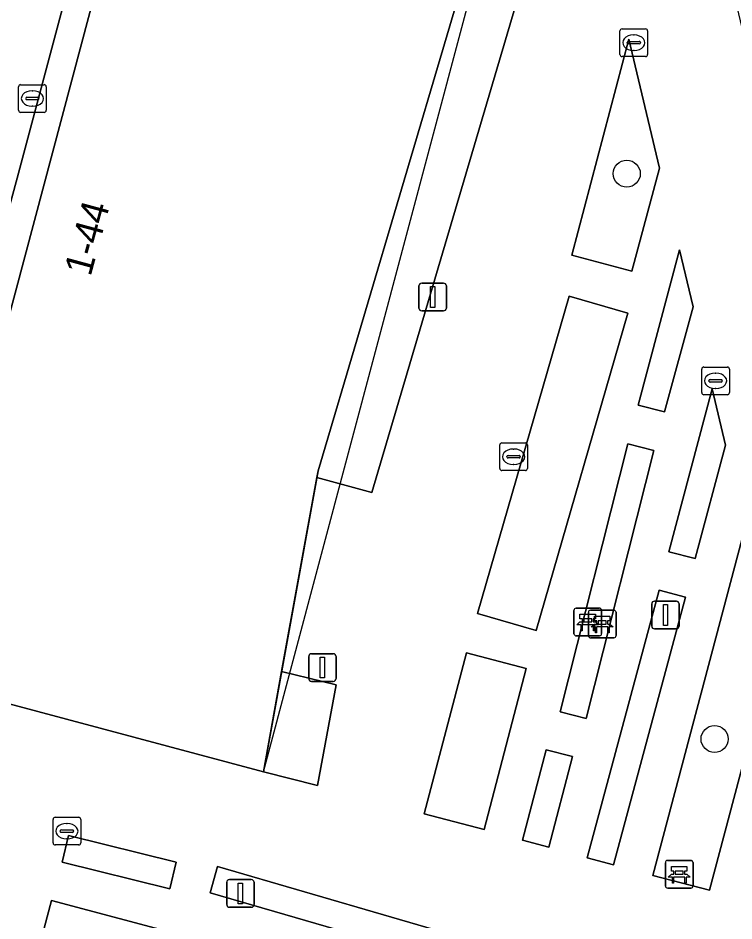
# Model space of a CAD drawing. Extents: x 160675 to 161153, y 383241 to 383714.
# Drawn here: x 160862.26 to 160888.14, y 383503.84 to 383536.47 of the extents above; entities that cross this region are included whole.
import ezdxf

# ---------------------------------------------------------------- set-up
doc = ezdxf.new("R2010")
doc.units = 0
for name, color, linetype in [('IMGEO_Bank', 7, 'Continuous'), ('IMGEO_Boom', 7, 'Continuous'), ('IMGEO_Groenvoorziening', 7, 'Continuous'), ('IMGEO_Kolk', 7, 'Continuous'), ('IMGEO_Lichtmast', 7, 'Continuous'), ('IMGEO_Pand', 7, 'Continuous'), ('IMGEO_Pand_nummerreeks', 7, 'Continuous'), ('IMGEO_Pand_overbouw', 7, 'Continuous'), ('IMGEO_Terreindeel_open', 7, 'Continuous'), ('IMGEO_Voetpad_open', 7, 'Continuous')]:
    doc.layers.add(name, color=color, linetype=linetype)

msp = doc.modelspace()

# ---------------------------------------------------------------- linework, layer by layer
at = {"layer": 'IMGEO_Bank'}
for p, q in [((160882.357, 383514.22), (160882.357, 383515.061)), ((160882.357, 383515.061), (160882.357, 383514.22)), ((160882.432, 383515.145), (160883.273, 383515.145)), ((160883.273, 383515.145), (160882.432, 383515.145)), ((160882.953, 383515.071), (160883.794, 383515.071)), ((160883.794, 383515.071), (160882.953, 383515.071)), ((160883.357, 383515.07), (160883.357, 383514.229)), ((160883.357, 383514.229), (160883.357, 383515.07)), ((160882.666, 383514.651), (160882.666, 383514.757)), ((160882.71, 383514.757), (160882.71, 383514.651)), ((160882.998, 383514.763), (160882.716, 383514.763)), ((160882.878, 383514.146), (160882.878, 383514.987)), ((160882.878, 383514.987), (160882.878, 383514.146)), ((160883.004, 383514.651), (160883.004, 383514.757)), ((160883.048, 383514.757), (160883.048, 383514.651)), ((160883.519, 383514.689), (160883.237, 383514.689)), ((160883.878, 383514.996), (160883.878, 383514.155)), ((160883.878, 383514.155), (160883.878, 383514.996)), ((160883.054, 383514.543), (160882.661, 383514.543)), ((160882.716, 383514.645), (160882.998, 383514.645)), ((160883.575, 383514.469), (160883.182, 383514.469)), ((160883.187, 383514.577), (160883.187, 383514.683)), ((160883.231, 383514.683), (160883.231, 383514.577)), ((160883.237, 383514.571), (160883.519, 383514.571)), ((160883.525, 383514.577), (160883.525, 383514.683)), ((160883.569, 383514.683), (160883.569, 383514.577)), ((160883.282, 383514.145), (160882.441, 383514.145)), ((160882.441, 383514.145), (160883.282, 383514.145)), ((160883.803, 383514.071), (160882.962, 383514.071)), ((160882.962, 383514.071), (160883.803, 383514.071)), ((160885.661, 383505.101), (160885.661, 383505.942)), ((160885.661, 383505.942), (160885.661, 383505.101)), ((160885.736, 383506.026), (160886.577, 383506.026)), ((160886.577, 383506.026), (160885.736, 383506.026)), ((160886.661, 383505.951), (160886.661, 383505.11)), ((160886.661, 383505.11), (160886.661, 383505.951)), ((160885.97, 383505.532), (160885.97, 383505.638)), ((160886.014, 383505.638), (160886.014, 383505.532)), ((160886.302, 383505.644), (160886.02, 383505.644)), ((160886.308, 383505.532), (160886.308, 383505.638)), ((160886.352, 383505.638), (160886.352, 383505.532)), ((160886.358, 383505.424), (160885.965, 383505.424)), ((160886.02, 383505.526), (160886.302, 383505.526)), ((160886.586, 383505.026), (160885.745, 383505.026)), ((160885.745, 383505.026), (160886.586, 383505.026))]:
    msp.add_line(p, q, dxfattribs=at)
for points in [[(160882.66, 383514.763), (160882.574, 383514.763), (160882.574, 383514.924), (160883.137, 383514.924), (160883.137, 383514.763), (160883.054, 383514.763)], [(160883.181, 383514.689), (160883.095, 383514.689), (160883.095, 383514.85), (160883.658, 383514.85), (160883.658, 383514.689), (160883.575, 383514.689)], [(160882.604, 383514.543), (160882.462, 383514.543), (160882.574, 383514.645), (160882.66, 383514.645)], [(160882.654, 383514.536), (160882.654, 383514.329), (160882.611, 383514.329), (160882.611, 383514.536)], [(160883.125, 383514.469), (160882.983, 383514.469), (160883.095, 383514.571), (160883.181, 383514.571)], [(160883.054, 383514.645), (160883.137, 383514.645), (160883.249, 383514.543), (160883.11, 383514.543)], [(160883.104, 383514.536), (160883.104, 383514.329), (160883.06, 383514.329), (160883.06, 383514.536)], [(160883.175, 383514.462), (160883.175, 383514.255), (160883.132, 383514.255), (160883.132, 383514.462)], [(160883.575, 383514.571), (160883.658, 383514.571), (160883.77, 383514.469), (160883.631, 383514.469)], [(160883.625, 383514.462), (160883.625, 383514.255), (160883.581, 383514.255), (160883.581, 383514.462)], [(160885.964, 383505.644), (160885.878, 383505.644), (160885.878, 383505.805), (160886.441, 383505.805), (160886.441, 383505.644), (160886.358, 383505.644)], [(160885.908, 383505.424), (160885.766, 383505.424), (160885.878, 383505.526), (160885.964, 383505.526)], [(160885.958, 383505.417), (160885.958, 383505.21), (160885.915, 383505.21), (160885.915, 383505.417)], [(160886.358, 383505.526), (160886.441, 383505.526), (160886.553, 383505.424), (160886.414, 383505.424)], [(160886.408, 383505.417), (160886.408, 383505.21), (160886.364, 383505.21), (160886.364, 383505.417)]]:
    msp.add_lwpolyline(points, dxfattribs=at)
for centre, radius, start, end in [((160882.435, 383515.067), 0.0779, 92.4484, 184.2845), ((160882.435, 383515.067), 0.0779, 92.4484, 184.2845), ((160882.956, 383514.993), 0.0779, 92.4484, 184.2845), ((160882.956, 383514.993), 0.0779, 92.4484, 184.2845), ((160883.279, 383515.067), 0.0779, 2.4484, 94.2845), ((160883.279, 383515.067), 0.0779, 2.4484, 94.2845), ((160883.8, 383514.993), 0.0779, 2.4484, 94.2845), ((160883.8, 383514.993), 0.0779, 2.4484, 94.2845), ((160882.659, 383514.756), 0.00671, 2.8957, 87.1043), ((160882.716, 383514.756), 0.00671, 92.8957, 177.1043), ((160882.998, 383514.756), 0.00671, 2.8957, 87.1043), ((160883.055, 383514.756), 0.00671, 92.8957, 177.1043), ((160883.18, 383514.682), 0.00671, 2.8957, 87.1043), ((160883.237, 383514.682), 0.00671, 92.8957, 177.1043), ((160883.519, 383514.682), 0.00671, 2.8957, 87.1043), ((160883.576, 383514.682), 0.00671, 92.8957, 177.1043), ((160882.604, 383514.536), 0.00671, 2.8957, 87.1043), ((160882.661, 383514.536), 0.00671, 92.8957, 177.1043), ((160882.659, 383514.652), 0.00671, 272.8957, 357.1043), ((160882.716, 383514.652), 0.00671, 182.8957, 267.1043), ((160882.998, 383514.652), 0.00671, 272.8957, 357.1043), ((160883.055, 383514.652), 0.00671, 182.8957, 267.1043), ((160883.053, 383514.536), 0.00671, 2.8957, 87.1043), ((160883.11, 383514.536), 0.00671, 92.8957, 177.1043), ((160883.125, 383514.462), 0.00671, 2.8957, 87.1043), ((160883.182, 383514.462), 0.00671, 92.8957, 177.1043), ((160883.18, 383514.578), 0.00671, 272.8957, 357.1043), ((160883.237, 383514.578), 0.00671, 182.8957, 267.1043), ((160883.519, 383514.578), 0.00671, 272.8957, 357.1043), ((160883.576, 383514.578), 0.00671, 182.8957, 267.1043), ((160883.574, 383514.462), 0.00671, 2.8957, 87.1043), ((160883.631, 383514.462), 0.00671, 92.8957, 177.1043), ((160882.435, 383514.223), 0.0779, 182.4484, 274.2845), ((160882.435, 383514.223), 0.0779, 182.4484, 274.2845), ((160882.956, 383514.149), 0.0779, 182.4484, 274.2845), ((160882.956, 383514.149), 0.0779, 182.4484, 274.2845), ((160883.279, 383514.223), 0.0779, 272.4484, 4.2845), ((160883.279, 383514.223), 0.0779, 272.4484, 4.2845), ((160883.8, 383514.149), 0.0779, 272.4484, 4.2845), ((160883.8, 383514.149), 0.0779, 272.4484, 4.2845), ((160885.739, 383505.948), 0.0779, 92.4484, 184.2845), ((160885.739, 383505.948), 0.0779, 92.4484, 184.2845), ((160886.583, 383505.948), 0.0779, 2.4484, 94.2845), ((160886.583, 383505.948), 0.0779, 2.4484, 94.2845), ((160885.963, 383505.637), 0.00671, 2.8957, 87.1043), ((160886.02, 383505.637), 0.00671, 92.8957, 177.1043), ((160886.302, 383505.637), 0.00671, 2.8957, 87.1043), ((160886.359, 383505.637), 0.00671, 92.8957, 177.1043), ((160885.908, 383505.417), 0.00671, 2.8957, 87.1043), ((160885.965, 383505.417), 0.00671, 92.8957, 177.1043), ((160885.963, 383505.533), 0.00671, 272.8957, 357.1043), ((160886.02, 383505.533), 0.00671, 182.8957, 267.1043), ((160886.302, 383505.533), 0.00671, 272.8957, 357.1043), ((160886.359, 383505.533), 0.00671, 182.8957, 267.1043), ((160886.357, 383505.417), 0.00671, 2.8957, 87.1043), ((160886.414, 383505.417), 0.00671, 92.8957, 177.1043), ((160885.739, 383505.104), 0.0779, 182.4484, 274.2845), ((160885.739, 383505.104), 0.0779, 182.4484, 274.2845), ((160886.583, 383505.104), 0.0779, 272.4484, 4.2845), ((160886.583, 383505.104), 0.0779, 272.4484, 4.2845)]:
    msp.add_arc(centre, radius, start, end, dxfattribs=at)
at = {"layer": 'IMGEO_Boom'}
for centre in [(160884.265, 383530.85), (160887.439, 383510.414)]:
    msp.add_circle(centre, 0.489, dxfattribs=at)
at = {"layer": 'IMGEO_Groenvoorziening'}
for points in [[(160882.404, 383551.516), (160882.765, 383552.718), (160867.046, 383548.766), (160862.229, 383530.692), (160857.402, 383512.924), (160858.445, 383512.624), (160866.56, 383543.07), (160867.863, 383547.958), (160869.136, 383548.269)], [(160885.452, 383531.052), (160884.337, 383535.716), (160882.275, 383527.908), (160884.45, 383527.328)], [(160886.165, 383528.095), (160884.676, 383522.483), (160885.625, 383522.243), (160886.664, 383526.034)], [(160880.989, 383514.338), (160884.301, 383525.812), (160882.182, 383526.424), (160878.87, 383514.95)], [(160886.734, 383516.939), (160887.837, 383521.04), (160887.355, 383523.068), (160885.788, 383517.177)], [(160884.3, 383521.082), (160881.855, 383511.395), (160882.802, 383511.156), (160885.247, 383520.843)], [(160888.545, 383518.071), (160885.21, 383505.485), (160887.26, 383504.948), (160889.58, 383513.712)], [(160882.838, 383506.122), (160883.787, 383505.867), (160886.389, 383515.541), (160885.44, 383515.796)], [(160876.945, 383507.705), (160879.106, 383507.14), (160880.632, 383512.969), (160878.471, 383513.535)], [(160871.79, 383512.852), (160871.132, 383509.231), (160873.089, 383508.73), (160873.758, 383512.376)], [(160882.309, 383509.777), (160881.356, 383510.028), (160880.496, 383506.755), (160881.449, 383506.505)], [(160863.855, 383505.962), (160867.746, 383505), (160867.984, 383505.963), (160864.093, 383506.925)], [(160882.056, 383502.15), (160869.476, 383505.805), (160869.202, 383504.86), (160881.782, 383501.206)], [(160863.476, 383504.573), (160862.947, 383502.579), (160875.539, 383499.24), (160876.068, 383501.233)]]:
    msp.add_lwpolyline(points, close=True, dxfattribs=at)
at = {"layer": 'IMGEO_Kolk'}
for p, q in [((160884.018, 383535.157), (160884.018, 383536.009)), ((160884.093, 383536.083), (160884.945, 383536.083)), ((160885.019, 383536.009), (160885.019, 383535.157)), ((160884.277, 383535.577), (160884.277, 383535.589)), ((160884.32, 383535.626), (160884.718, 383535.626)), ((160884.506, 383535.863), (160884.531, 383535.863)), ((160884.761, 383535.589), (160884.761, 383535.577)), ((160884.715, 383535.54), (160884.317, 383535.54)), ((160884.529, 383535.303), (160884.504, 383535.303)), ((160884.945, 383535.083), (160884.093, 383535.083)), ((160862.282, 383533.14), (160862.282, 383533.992)), ((160862.357, 383534.066), (160863.209, 383534.066)), ((160863.283, 383533.992), (160863.283, 383533.14)), ((160862.77, 383533.846), (160862.795, 383533.846)), ((160862.541, 383533.56), (160862.541, 383533.572)), ((160862.979, 383533.523), (160862.581, 383533.523)), ((160862.584, 383533.609), (160862.982, 383533.609)), ((160863.025, 383533.572), (160863.025, 383533.56)), ((160863.209, 383533.066), (160862.357, 383533.066)), ((160862.793, 383533.286), (160862.768, 383533.286)), ((160887.05, 383523.861), (160887.902, 383523.861)), ((160886.975, 383522.935), (160886.975, 383523.787)), ((160887.463, 383523.641), (160887.488, 383523.641)), ((160887.976, 383523.787), (160887.976, 383522.935)), ((160887.234, 383523.355), (160887.234, 383523.367)), ((160887.672, 383523.318), (160887.274, 383523.318)), ((160887.277, 383523.404), (160887.675, 383523.404)), ((160887.718, 383523.367), (160887.718, 383523.355)), ((160887.902, 383522.861), (160887.05, 383522.861)), ((160887.486, 383523.081), (160887.461, 383523.081)), ((160879.675, 383520.191), (160879.675, 383521.043)), ((160879.75, 383521.117), (160880.602, 383521.117)), ((160880.163, 383520.897), (160880.188, 383520.897)), ((160880.676, 383521.043), (160880.676, 383520.191)), ((160879.934, 383520.611), (160879.934, 383520.623)), ((160880.372, 383520.574), (160879.974, 383520.574)), ((160879.977, 383520.66), (160880.375, 383520.66)), ((160880.418, 383520.623), (160880.418, 383520.611)), ((160880.186, 383520.337), (160880.161, 383520.337)), ((160880.602, 383520.117), (160879.75, 383520.117)), ((160863.529, 383506.658), (160863.529, 383507.51)), ((160863.604, 383507.584), (160864.456, 383507.584)), ((160864.53, 383507.51), (160864.53, 383506.658)), ((160864.017, 383507.364), (160864.042, 383507.364)), ((160863.788, 383507.078), (160863.788, 383507.09)), ((160864.226, 383507.041), (160863.828, 383507.041)), ((160863.831, 383507.127), (160864.229, 383507.127)), ((160864.272, 383507.09), (160864.272, 383507.078)), ((160864.456, 383506.584), (160863.604, 383506.584)), ((160864.04, 383506.804), (160864.015, 383506.804))]:
    msp.add_line(p, q, dxfattribs=at)
for points in [[(160884.018, 383535.157), (160884.018, 383536.009)], [(160884.093, 383536.083), (160884.945, 383536.083)], [(160885.019, 383536.009), (160885.019, 383535.157)], [(160884.945, 383535.083), (160884.093, 383535.083)], [(160862.282, 383533.14), (160862.282, 383533.992)], [(160862.357, 383534.066), (160863.209, 383534.066)], [(160863.283, 383533.992), (160863.283, 383533.14)], [(160863.209, 383533.066), (160862.357, 383533.066)], [(160887.05, 383523.861), (160887.902, 383523.861)], [(160886.975, 383522.935), (160886.975, 383523.787)], [(160887.976, 383523.787), (160887.976, 383522.935)], [(160887.902, 383522.861), (160887.05, 383522.861)], [(160879.675, 383520.191), (160879.675, 383521.043)], [(160879.75, 383521.117), (160880.602, 383521.117)], [(160880.676, 383521.043), (160880.676, 383520.191)], [(160880.602, 383520.117), (160879.75, 383520.117)], [(160863.529, 383506.658), (160863.529, 383507.51)], [(160863.604, 383507.584), (160864.456, 383507.584)], [(160864.53, 383507.51), (160864.53, 383506.658)], [(160864.456, 383506.584), (160863.604, 383506.584)]]:
    msp.add_lwpolyline(points, dxfattribs=at)
for centre, radius, start, end in [((160884.095, 383536.007), 0.0765, 91.552, 178.448), ((160884.095, 383536.007), 0.0765, 91.552, 178.448), ((160884.943, 383536.007), 0.0765, 1.552, 88.448), ((160884.943, 383536.007), 0.0765, 1.552, 88.448), ((160884.317, 383535.586), 0.0403, 85.8775, 175.7526), ((160884.314, 383535.576), 0.0366, 178.938, 274.7102), ((160884.718, 383535.583), 0.043, 264.8664, 352.4533), ((160884.722, 383535.588), 0.0386, 1.7309, 96.639), ((160884.095, 383535.159), 0.0765, 181.552, 268.448), ((160884.095, 383535.159), 0.0765, 181.552, 268.448), ((160884.943, 383535.159), 0.0765, 271.552, 358.448), ((160884.943, 383535.159), 0.0765, 271.552, 358.448), ((160862.359, 383533.99), 0.0765, 91.552, 178.448), ((160862.359, 383533.99), 0.0765, 91.552, 178.448), ((160863.207, 383533.99), 0.0765, 1.552, 88.448), ((160863.207, 383533.99), 0.0765, 1.552, 88.448), ((160862.581, 383533.569), 0.0403, 85.8775, 175.7526), ((160862.578, 383533.559), 0.0366, 178.938, 274.7102), ((160862.982, 383533.566), 0.043, 264.8664, 352.4533), ((160862.986, 383533.571), 0.0386, 1.7309, 96.639), ((160862.359, 383533.142), 0.0765, 181.552, 268.448), ((160862.359, 383533.142), 0.0765, 181.552, 268.448), ((160863.207, 383533.142), 0.0765, 271.552, 358.448), ((160863.207, 383533.142), 0.0765, 271.552, 358.448), ((160887.052, 383523.785), 0.0765, 91.552, 178.448), ((160887.052, 383523.785), 0.0765, 91.552, 178.448), ((160887.9, 383523.785), 0.0765, 1.552, 88.448), ((160887.9, 383523.785), 0.0765, 1.552, 88.448), ((160887.274, 383523.364), 0.0403, 85.8775, 175.7526), ((160887.271, 383523.354), 0.0366, 178.938, 274.7102), ((160887.675, 383523.361), 0.043, 264.8664, 352.4533), ((160887.679, 383523.366), 0.0386, 1.7309, 96.639), ((160887.052, 383522.937), 0.0765, 181.552, 268.448), ((160887.052, 383522.937), 0.0765, 181.552, 268.448), ((160887.9, 383522.937), 0.0765, 271.552, 358.448), ((160887.9, 383522.937), 0.0765, 271.552, 358.448), ((160879.752, 383521.041), 0.0765, 91.552, 178.448), ((160879.752, 383521.041), 0.0765, 91.552, 178.448), ((160880.6, 383521.041), 0.0765, 1.552, 88.448), ((160880.6, 383521.041), 0.0765, 1.552, 88.448), ((160879.974, 383520.62), 0.0403, 85.8775, 175.7526), ((160879.971, 383520.61), 0.0366, 178.938, 274.7102), ((160880.375, 383520.617), 0.043, 264.8664, 352.4533), ((160880.379, 383520.622), 0.0386, 1.7309, 96.639), ((160879.752, 383520.193), 0.0765, 181.552, 268.448), ((160879.752, 383520.193), 0.0765, 181.552, 268.448), ((160880.6, 383520.193), 0.0765, 271.552, 358.448), ((160880.6, 383520.193), 0.0765, 271.552, 358.448), ((160863.606, 383507.508), 0.0765, 91.552, 178.448), ((160863.606, 383507.508), 0.0765, 91.552, 178.448), ((160864.454, 383507.508), 0.0765, 1.552, 88.448), ((160864.454, 383507.508), 0.0765, 1.552, 88.448), ((160863.828, 383507.087), 0.0403, 85.8775, 175.7526), ((160863.825, 383507.077), 0.0366, 178.938, 274.7102), ((160864.229, 383507.084), 0.043, 264.8664, 352.4533), ((160864.233, 383507.089), 0.0386, 1.7309, 96.639), ((160863.606, 383506.66), 0.0765, 181.552, 268.448), ((160863.606, 383506.66), 0.0765, 181.552, 268.448), ((160864.454, 383506.66), 0.0765, 271.552, 358.448), ((160864.454, 383506.66), 0.0765, 271.552, 358.448)]:
    msp.add_arc(centre, radius, start, end, dxfattribs=at)
for centre, major_axis, ratio, start_param, end_param in [((160884.505, 383535.583), (-0.387, 0.002), 0.722429, 4.712389, 7.853982), ((160884.53, 383535.583), (-0.39, 0.002), 0.717154, 1.570796, 4.712389), ((160862.769, 383533.566), (-0.387, 0.002), 0.722429, 4.712389, 7.853982), ((160862.794, 383533.566), (-0.39, 0.002), 0.717154, 1.570796, 4.712389), ((160887.462, 383523.361), (-0.387, 0.002), 0.722429, 4.712389, 7.853982), ((160887.487, 383523.361), (-0.39, 0.002), 0.717154, 1.570796, 4.712389), ((160880.162, 383520.617), (-0.387, 0.002), 0.722429, 4.712389, 7.853982), ((160880.187, 383520.617), (-0.39, 0.002), 0.717154, 1.570796, 4.712389), ((160864.016, 383507.084), (-0.387, 0.002), 0.722429, 4.712389, 7.853982), ((160864.041, 383507.084), (-0.39, 0.002), 0.717154, 1.570796, 4.712389)]:
    msp.add_ellipse(centre, major_axis=major_axis, ratio=ratio, start_param=start_param, end_param=end_param, dxfattribs=at)
at = {"layer": 'IMGEO_Lichtmast'}
for p, q in [((160876.754, 383525.992), (160876.754, 383526.792)), ((160876.754, 383526.792), (160876.754, 383525.992)), ((160876.854, 383526.892), (160877.644, 383526.892)), ((160877.644, 383526.892), (160876.854, 383526.892)), ((160877.744, 383526.792), (160877.744, 383525.992)), ((160877.744, 383525.992), (160877.744, 383526.792)), ((160877.644, 383525.892), (160876.854, 383525.892)), ((160876.854, 383525.892), (160877.644, 383525.892)), ((160885.268, 383515.398), (160886.058, 383515.398)), ((160886.058, 383515.398), (160885.268, 383515.398)), ((160885.168, 383514.498), (160885.168, 383515.298)), ((160885.168, 383515.298), (160885.168, 383514.498)), ((160886.158, 383515.298), (160886.158, 383514.498)), ((160886.158, 383514.498), (160886.158, 383515.298)), ((160886.058, 383514.398), (160885.268, 383514.398)), ((160885.268, 383514.398), (160886.058, 383514.398)), ((160872.768, 383512.599), (160872.768, 383513.399)), ((160872.768, 383513.399), (160872.768, 383512.599)), ((160872.868, 383513.499), (160873.658, 383513.499)), ((160873.658, 383513.499), (160872.868, 383513.499)), ((160873.758, 383513.399), (160873.758, 383512.599)), ((160873.758, 383512.599), (160873.758, 383513.399)), ((160873.658, 383512.499), (160872.868, 383512.499)), ((160872.868, 383512.499), (160873.658, 383512.499)), ((160869.805, 383504.435), (160869.805, 383505.235)), ((160869.805, 383505.235), (160869.805, 383504.435)), ((160869.905, 383505.335), (160870.695, 383505.335)), ((160870.695, 383505.335), (160869.905, 383505.335)), ((160870.795, 383505.235), (160870.795, 383504.435)), ((160870.795, 383504.435), (160870.795, 383505.235)), ((160870.695, 383504.335), (160869.905, 383504.335)), ((160869.905, 383504.335), (160870.695, 383504.335))]:
    msp.add_line(p, q, dxfattribs=at)
for points in [[(160877.174, 383526.767), (160877.324, 383526.767), (160877.324, 383526.017), (160877.174, 383526.017), (160877.174, 383526.767)], [(160885.588, 383515.273), (160885.738, 383515.273), (160885.738, 383514.523), (160885.588, 383514.523), (160885.588, 383515.273)], [(160873.188, 383513.374), (160873.338, 383513.374), (160873.338, 383512.624), (160873.188, 383512.624), (160873.188, 383513.374)], [(160870.225, 383505.21), (160870.375, 383505.21), (160870.375, 383504.46), (160870.225, 383504.46), (160870.225, 383505.21)]]:
    msp.add_lwpolyline(points, dxfattribs=at)
for centre, start, end in [((160876.854, 383526.792), 90, 180), ((160876.854, 383526.792), 90, 180), ((160877.644, 383526.792), 0, 90), ((160877.644, 383526.792), 360, 90), ((160876.854, 383525.992), 180, 270), ((160876.854, 383525.992), 180, 270), ((160877.644, 383525.992), 270, 0), ((160877.644, 383525.992), 270, 0), ((160885.268, 383515.298), 90, 180), ((160885.268, 383515.298), 90, 180), ((160886.058, 383515.298), 0, 90), ((160886.058, 383515.298), 360, 90), ((160885.268, 383514.498), 180, 270), ((160885.268, 383514.498), 180, 270), ((160886.058, 383514.498), 270, 0), ((160886.058, 383514.498), 270, 0), ((160872.868, 383513.399), 90, 180), ((160872.868, 383513.399), 90, 180), ((160873.658, 383513.399), 0, 90), ((160873.658, 383513.399), 360, 90), ((160872.868, 383512.599), 180, 270), ((160872.868, 383512.599), 180, 270), ((160873.658, 383512.599), 270, 0), ((160873.658, 383512.599), 270, 0), ((160869.905, 383505.235), 90, 180), ((160869.905, 383505.235), 90, 180), ((160870.695, 383505.235), 0, 90), ((160870.695, 383505.235), 360, 90), ((160869.905, 383504.435), 180, 270), ((160869.905, 383504.435), 180, 270), ((160870.695, 383504.435), 270, 0), ((160870.695, 383504.435), 270, 0)]:
    msp.add_arc(centre, 0.1, start, end, dxfattribs=at)
at = {"layer": 'IMGEO_Pand'}
msp.add_lwpolyline([(160879.332, 383541.136), (160881.532, 383548.57), (160882.162, 383550.698), (160882.404, 383551.516), (160869.136, 383548.269), (160867.863, 383547.958), (160866.56, 383543.07), (160858.445, 383512.624), (160860.534, 383512.065), (160871.132, 383509.231), (160871.79, 383512.852), (160873.064, 383519.865), (160873.107, 383520.103)], close=True, dxfattribs=at)
at = {"layer": 'IMGEO_Pand_overbouw'}
msp.add_lwpolyline([(160882.404, 383551.516), (160873.107, 383520.103), (160871.132, 383509.231)], close=True, dxfattribs=at)
at = {"layer": 'IMGEO_Terreindeel_open'}
msp.add_lwpolyline([(160879.332, 383541.136), (160873.107, 383520.103), (160873.064, 383519.865), (160875.055, 383519.322), (160881.31, 383540.557)], close=True, dxfattribs=at)
at = {"layer": 'IMGEO_Voetpad_open'}
for points in [[(160861.525, 383537.121), (160855.717, 383527.187), (160854.143, 383524.612), (160853.325, 383523.422), (160853.08, 383523.019), (160852.899, 383522.475), (160851.327, 383517.544), (160850.446, 383514.813), (160850.389, 383514.634), (160857.402, 383512.924), (160862.229, 383530.692), (160867.046, 383548.766), (160871.287, 383559.494)], [(160905.085, 383509.775), (160897.386, 383507.933), (160895.279, 383507.435), (160890.493, 383527.494), (160886.195, 383545.514), (160886.275, 383545.773), (160888.011, 383551.386), (160884.968, 383552.305), (160883.193, 383546.357), (160882.995, 383546.404), (160883.474, 383547.996), (160881.532, 383548.57), (160879.332, 383541.136), (160881.31, 383540.557), (160875.055, 383519.322), (160873.064, 383519.865), (160871.79, 383512.852), (160873.758, 383512.376), (160873.089, 383508.73), (160871.132, 383509.231), (160860.534, 383512.065)]]:
    msp.add_lwpolyline(points, dxfattribs=at)
for points in [[(160884.337, 383535.716), (160885.452, 383531.052), (160884.45, 383527.328), (160882.275, 383527.908)], [(160886.165, 383528.095), (160886.664, 383526.034), (160885.625, 383522.243), (160884.676, 383522.483)], [(160882.182, 383526.424), (160884.301, 383525.812), (160880.989, 383514.338), (160878.87, 383514.95)], [(160887.355, 383523.068), (160887.837, 383521.04), (160886.734, 383516.939), (160885.788, 383517.177)], [(160884.3, 383521.082), (160885.247, 383520.843), (160882.802, 383511.156), (160881.855, 383511.395)], [(160888.545, 383518.071), (160889.58, 383513.712), (160887.26, 383504.948), (160885.21, 383505.485)], [(160882.838, 383506.122), (160885.44, 383515.796), (160886.389, 383515.541), (160883.787, 383505.867)], [(160876.945, 383507.705), (160878.471, 383513.535), (160880.632, 383512.969), (160879.106, 383507.14)], [(160881.356, 383510.028), (160882.309, 383509.777), (160881.449, 383506.505), (160880.496, 383506.755)], [(160863.855, 383505.962), (160864.093, 383506.925), (160867.984, 383505.963), (160867.746, 383505)], [(160869.476, 383505.805), (160882.056, 383502.15), (160881.782, 383501.206), (160869.202, 383504.86)], [(160863.476, 383504.573), (160876.068, 383501.233), (160875.539, 383499.24), (160862.947, 383502.579)]]:
    msp.add_lwpolyline(points, close=True, dxfattribs=at)

# ---------------------------------------------------------------- texts
at = {"layer": 'IMGEO_Pand_nummerreeks'}
msp.add_text('1-44', height=1, rotation=74.8799, dxfattribs=at).set_placement((160864.885, 383527.106))

doc.saveas('drawing.dxf')
